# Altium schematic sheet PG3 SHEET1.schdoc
size B; Date: 2/10/2009; ApprovedBy: Touraj; DrawnBy: Juan A. Nadal; Engineer: Touraj; Organization: ActiveWave; Address1: 902 Clint Moore Rd., Suite 118; Address2: Boca Raton; Address3: FL, 33487; Address4: 561-999-9422; DocumentNumber: 3; Revision: 18; SheetNumber: 3; SheetTotal: 4; PageSetup: Record=PageOptions|CenterHorizontal=True|CenterVertical=True|PrintScale=0.70|XCorrection=1.00|YCorrection=1.00|PrintKind=0|BorderSize=5000000|LeftOffset=0|BottomOffset=0|Orientation=2|PaperLength=1000|PaperWidth=1000|Scale=100|PaperSource=7|PrintQuality=-4|MediaType=1|DitherType=10|PaperKind=Letter|PrintScaleMode=1; Project: Tag105
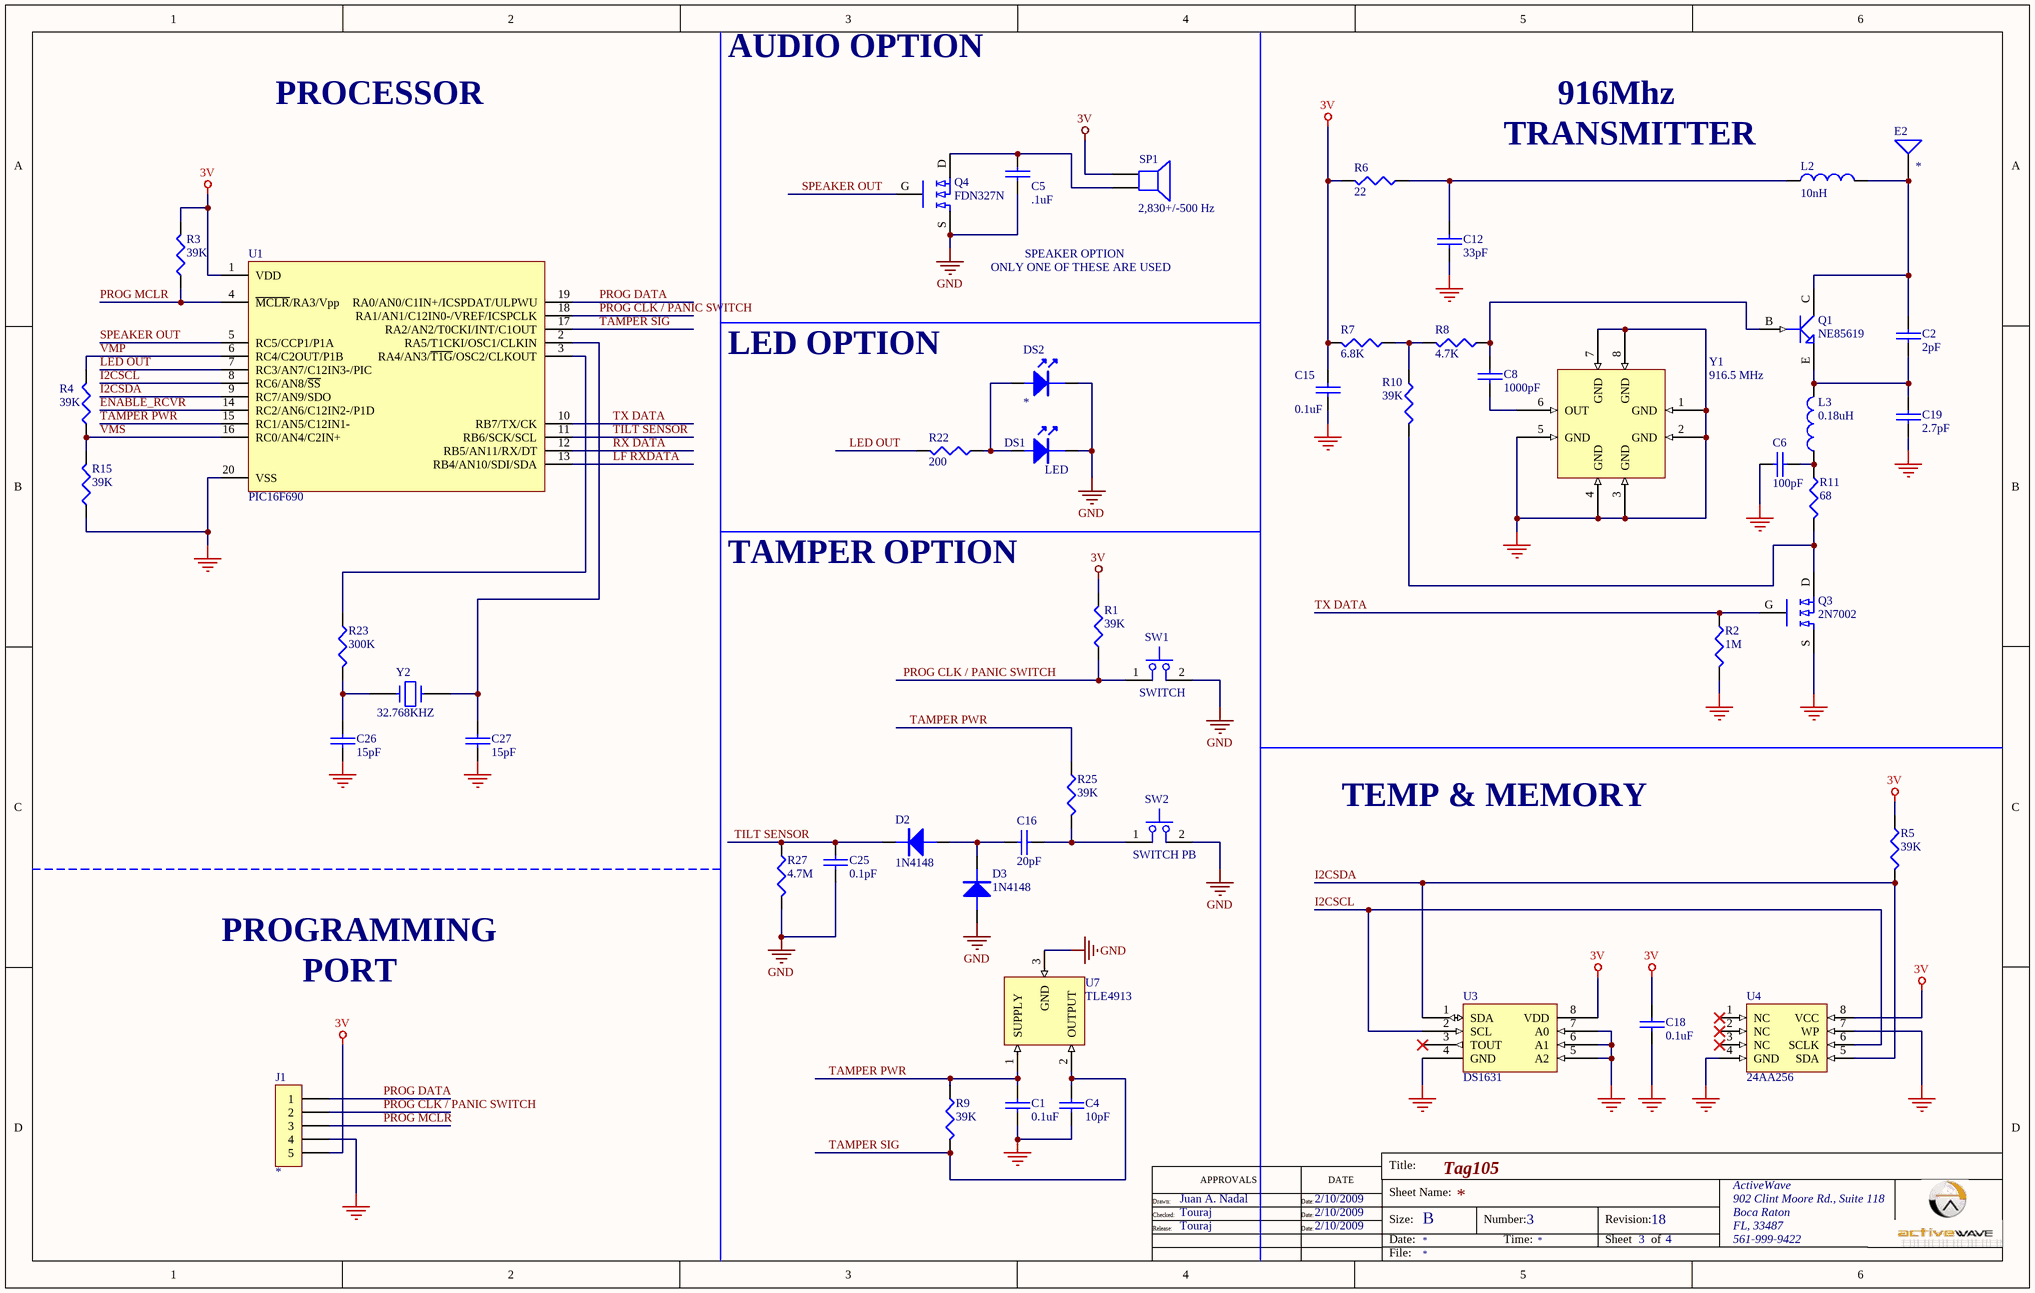
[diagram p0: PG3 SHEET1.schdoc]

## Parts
C1  0.1uF  [0603]
C2  2pF  [0603]
C4  10pF  [0603]
C5  .1uF  [0603]
C6  100pF  [0603]
C8  1000pF  [0603]
C12  33pF  [0603]
C15  0.1uF  [0603]
C16  20pF  [0603]
C18  0.1uF  [0603]
C19  2.7pF  [0603]
C25  0.1pF  [0603]
C26  15pF  [0603]
C27  15pF  [0603]
D2  1N4148  [sod123_021405]
D3  1N4148  [sod123_021405]
DS1  LED  [404-1032-2-ND]
DS2  *  [LCE-358RP]
E2  *  [Antenna1]
J1  *  [1X5 HEADER]
L2  10nH  [0603]
L3  0.18uH  [0603]
Q1  NE85619  [3 PIN ULTRA SUPER MINI MOLD]
Q3  2N7002  [SOT23 FET]
Q4  FDN327N  [SOT23 FET]
R1  39K  [0603]
R2  1M
R3  39K  [0603]
R4  39K  [0603]
R5  39K  [0603]
R6  22
R7  6.8K
R8  4.7K
R9  39K  [0603]
R10  39K  [0603]
R11  68
R15  39K  [0603]
R22  200  [0603]
R23  300K  [0603]
R25  39K  [0603]
R27  4.7M  [0603]
SP1  2,830+/-500 Hz  [SMT-1028-S-R]
SW1  SWITCH  [SWITCH PB REVERSED_082907]
SW2  SWITCH PB  [SQ-SEN-200]
U1  PIC16F690  [SSOP20 WIDE]
U3  DS1631  [SO8 SMALL]
U4  24AA256  [SO8]
U7  TLE4913  [SOT23W]
Y1  916.5 MHz  [RESONATOR]
Y2  32.768KHZ  [CRYSTAL ABRACON ABS07]

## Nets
3V: C15.1 C18.1 J1.5 R1.2 R3.2 R5.1 R6.2 R7.2 SP1.1 U1.1(VDD) U3.8(VDD) U4.8(VCC)
GND: C1.2 C4.2 C5.2 C6.2 C12.2 C15.2 C18.2 C19.2 C25.2 C26.2 C27.2 D3.A DS1.K DS2.2 J1.4 Q3.S Q4.S R2.2 R15.1 R27.2 SW1.2 SW2.2 U1.20(VSS) U3.4(GND) U3.5(A2) U3.6(A1) U3.7(A0) U4.4(GND) U4.7(WP) U7.3(GND) Y1.1(GND) Y1.2(GND) Y1.3(GND) Y1.4(GND) Y1.5(GND) Y1.7(GND) Y1.8(GND)
ENABLE_RCVR: U1.14(RC2/AN6/C12IN2-/P1D)
I2CSCL: U1.8(RC6/AN8/~{SS}) U3.2(SCL) U4.6(SCLK)
I2CSDA: R5.2 U1.9(RC7/AN9/SDO) U3.1(SDA) U4.5(SDA)
LED OUT: R22.2 U1.7(RC3/AN7/C12IN3-/PIC)
LF RXDATA: U1.13(RB4/AN10/SDI/SDA)
PROG CLK / PANIC SWITCH: J1.2 R1.1 SW1.1 U1.18(RA1/AN1/C12IN0-/VREF/ICSPCLK)
PROG DATA: J1.1 U1.19(RA0/AN0/C1IN+/ICSPDAT/ULPWU)
PROG MCLR: J1.3 R3.1 U1.4(~{MCLR}/RA3/Vpp)
RX DATA: U1.12(RB5/AN11/RX/DT)
SPEAKER OUT: Q4.G U1.5(RC5/CCP1/P1A)
TAMPER PWR: C1.1 R9.1 R25.1 U1.15(RC1/AN5/C12IN1-) U7.1(SUPPLY)
TAMPER SIG: C4.1 R9.2 U1.17(RA2/AN2/T0CKI/INT/C1OUT) U7.2(OUTPUT)
TILT SENSOR: C25.1 D2.K R27.1 U1.11(RB6/SCK/SCL)
TX DATA: Q3.G R2.1 U1.10(RB7/TX/CK)
VMP: R4.2 U1.6(RC4/C2OUT/P1B)
VMS: R4.1 R15.2 U1.16(RC0/AN4/C2IN+)
NetC2_1: C2.1 E2.1 L2.2 Q1.C
NetC2_2: C2.2 C19.1 L3.2 Q1.E
NetC5_1: C5.1 Q4.D SP1.2
NetC6_1: C6.1 L3.1 R11.1
NetC8_1: C8.1 Q1.B R8.1
NetC8_2: C8.2 Y1.6(OUT)
NetC12_1: C12.1 L2.1 R6.1
NetC16_1: C16.1 R25.2 SW2.1
NetC16_2: C16.2 D2.A D3.K
NetC26_1: C26.1 R23.2 Y2.1
NetC27_1: C27.1 U1.2(RA5/T1CKI/OSC1/CLKIN) Y2.2
NetDS1_A: DS1.A DS2.1 R22.1
NetQ3_D: Q3.D R10.2 R11.2
NetR7_1: R7.1 R8.2 R10.1
NetR23_1: R23.1 U1.3(RA4/AN3/~{T1G}/OSC2/CLKOUT)

Not connected (* = marked no-connect by the designer): U3 3(TOUT)*; U4 1(NC)* 2(NC)* 3(NC)*

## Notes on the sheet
- AUDIO OPTION
- PROCESSOR
- TRANSMITTER
- 916Mhz
- ONLY ONE OF THESE ARE USED
- SPEAKER OPTION
- LED OPTION
- TAMPER OPTION
- TEMP & MEMORY
- PROGRAMMING
- PORT

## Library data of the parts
C1 C2 C4-C6 C8 C12 C15 C16 C18 C19 C25-C27 = CAP-0603: Capacitor
D2 D3 = DIODE
DS2 = LCE-358RP: X-Bring Red Power SMD LED Emitter; MANUFACTURER: L.C. LED
E2 = Antenna1
J1 = CON5-1: Connector
L2 L3 = INDUCTOR
Q1 = NE85619: TRANSISTOR NPN 1GHZ SMD; MANUFACTURER: ??????
Q3 = 2N7002: N-CHANNEL ENHANCEMENT MODE FIELD EFFECT TRANSISTOR; MANUFACTURER: FAIRCHILD
Q4 = FDN327N: 20V N-Channel MOSFET; MANUFACTURER: FAIRCHILD; ITEM-DESCRIPTION: N-CHANNEL 1.8 VGS SPECIFIED POWERTRENCH MOSFET
R1 R3-R5 R9 R10 R15 R22 R23 R25 R27 = RES-0603
R2 R6-R8 R11 = RES-0402
SP1 = SMT-1028-S-R: Surface Mount Transducer; MANUFACTURER: PUI Audio; ITEM-DESCRIPTION: Audio Indicators & Alerts EM 98dB 2830H 3.6Vpp
U1 = PIC16F690-E/P: Microcontrollers (MCU) 7KB FL 256R 18 I/O; MANUFACTURER: Microchip
U3 = DS1631: High-Precision Digital Thermometer and Thermostat; MANUFACTURER: DALLAS SEMICONDUCTOR; MFGR-P/N: ??????
U4 = 24AA256-I/P: 24AA256 32k Microchip Serial EEPROM
U7 = TLE4913: Low Power Hall Switch; MANUFACTURER: Infineon Technologies AG
Y1 = RESONATOR: 916.5 MHz Saw Resonator; MANUFACTURER: ??????
Y2 = CRYSTAL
